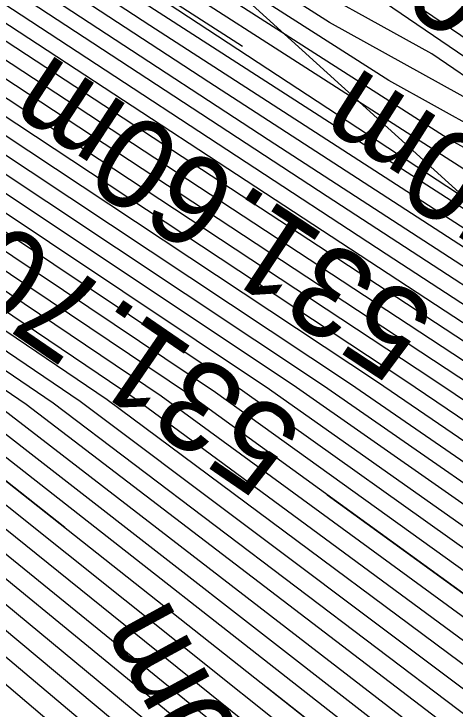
# Model space of a CAD drawing. Extents: x -866683 to -866410, y -1041951 to -1040252.
# Drawn here: x -866433.64 to -866432.173, y -1041927.226 to -1041924.913 of the extents above; entities that cross this region are included whole.
import ezdxf

# ---------------------------------------------------------------- set-up
doc = ezdxf.new("R2010")
doc.units = 0
for name, color, linetype in [('BREAKLINE', 7, 'Continuous'), ('V-VEDL', 7, 'Continuous'), ('V_po_cm', 7, 'Continuous')]:
    doc.layers.add(name, color=color, linetype=linetype)

msp = doc.modelspace()

# ---------------------------------------------------------------- linework, layer by layer
at = {"layer": 'BREAKLINE'}
msp.add_lwpolyline([(-866430.202, -1041927.282), (-866445.247, -1041913.64), (-866449.543, -1041926.354), (-866449.641, -1041934.033), (-866450.183, -1041936.864), (-866452.267, -1041937.851), (-866451.576, -1041945.087)], dxfattribs=at)
at = {"layer": 'V-VEDL'}
for points in [[(-866449.345, -1041907.5366), (-866448.9556, -1041907.8532), (-866448.4862, -1041908.0339), (-866448.3105, -1041908.3809), (-866448.4285, -1041908.8942), (-866448.8402, -1041909.5738), (-866449.0019, -1041910.1655), (-866448.9134, -1041910.6692), (-866448.5749, -1041911.085), (-866448.5335, -1041911.4362), (-866448.7893, -1041911.7228), (-866449.3421, -1041911.9448), (-866449.4057, -1041912.585), (-866448.98, -1041913.6435), (-866448.0652, -1041915.1203), (-866447.345, -1041916.0757), (-866446.8195, -1041916.5099), (-866446.4887, -1041916.4228), (-866444.7099, -1041917.3864), (-866441.483, -1041919.4008), (-866432.1333, -1041925.5308)], [(-866431.9788, -1041928.8199), (-866431.5928, -1041928.1776), (-866431.4675, -1041927.947), (-866431.4098, -1041927.8071), (-866431.4198, -1041927.7578), (-866431.4204, -1041927.6712), (-866431.4114, -1041927.5475), (-866431.3929, -1041927.3866), (-866433.06, -1041926.1783), (-866436.4127, -1041923.9225), (-866441.4509, -1041920.6192), (-866444.9601, -1041918.4567), (-866446.9402, -1041917.4347), (-866447.3913, -1041917.5535), (-866448.1079, -1041916.9614), (-866449.0899, -1041915.6585), (-866450.3375, -1041913.6448)], [(-866449.6588, -1041913.6442), (-866448.5775, -1041915.3894), (-866447.7264, -1041916.5186), (-866447.1054, -1041917.0317), (-866446.7144, -1041916.9288), (-866444.6833, -1041918.021), (-866441.0121, -1041920.3082), (-866435.7006, -1041923.7906), (-866432.1607, -1041926.1208), (-866430.3921, -1041927.2987), (-866430.3951, -1041927.3244), (-866430.3965, -1041927.3441), (-866430.3964, -1041927.358), (-866430.3948, -1041927.3658), (-866430.4041, -1041927.3882), (-866430.4241, -1041927.425), (-866430.4857, -1041927.5276)], [(-866449.6023, -1041915.9277), (-866448.4893, -1041917.4043), (-866447.6772, -1041918.0753), (-866447.1659, -1041917.9407), (-866445.2368, -1041918.8924), (-866441.8897, -1041920.9302), (-866437.1247, -1041924.0544), (-866433.9594, -1041926.2358), (-866432.3937, -1041927.4746), (-866432.4277, -1041927.7707), (-866432.4442, -1041927.9983), (-866432.4432, -1041928.1576), (-866432.4248, -1041928.2484), (-866432.531, -1041928.5059), (-866432.7616, -1041928.9302), (-866433.4719, -1041930.1123)]]:
    msp.add_lwpolyline(points, dxfattribs=at)
at = {"layer": 'V_po_cm'}
for points in [[(-866449.4813, -1041912.5658), (-866449.0479, -1041913.6436), (-866448.1164, -1041915.1472), (-866447.3831, -1041916.12), (-866446.8481, -1041916.5621), (-866446.5112, -1041916.4734), (-866444.7001, -1041917.4545), (-866441.4146, -1041919.5055), (-866436.6547, -1041922.6262), (-866433.3844, -1041924.7606), (-866431.6036, -1041925.9086), (-866431.3124, -1041926.0701), (-866431.0001, -1041926.2826), (-866430.6667, -1041926.546), (-866429.9578, -1041927.1745)], [(-866449.3301, -1041912.6042), (-866448.9122, -1041913.6435), (-866448.0139, -1041915.0933), (-866447.3068, -1041916.0314), (-866446.7909, -1041916.4577), (-866446.4661, -1041916.3722), (-866444.7196, -1041917.3183), (-866441.5514, -1041919.296), (-866436.9616, -1041922.3053), (-866433.7773, -1041924.3805), (-866431.9985, -1041925.5217), (-866431.6252, -1041925.7288), (-866431.2249, -1041926.0011), (-866430.7976, -1041926.3386), (-866429.889, -1041927.1442)], [(-866429.8546, -1041927.129), (-866430.8631, -1041926.2349), (-866431.3373, -1041925.8603), (-866431.7816, -1041925.5581), (-866432.1959, -1041925.3282), (-866433.9737, -1041924.1905), (-866437.115, -1041922.1448), (-866441.6199, -1041919.1913), (-866444.7294, -1041917.2502), (-866446.4435, -1041916.3216), (-866446.7623, -1041916.4055), (-866447.2687, -1041915.9871), (-866447.9627, -1041915.0664), (-866448.8443, -1041913.6434), (-866449.2545, -1041912.6234)], [(-866429.8202, -1041927.1139), (-866430.9285, -1041926.1313), (-866431.4498, -1041925.7195), (-866431.938, -1041925.3874), (-866432.3933, -1041925.1348), (-866434.1701, -1041924.0005), (-866437.2685, -1041921.9844), (-866441.6883, -1041919.0865), (-866444.7391, -1041917.1821), (-866446.4209, -1041916.271), (-866446.7337, -1041916.3534), (-866447.2305, -1041915.9429), (-866447.9114, -1041915.0395), (-866448.7764, -1041913.6433), (-866449.1788, -1041912.6426)], [(-866431.8295, -1041928.6907), (-866431.476, -1041928.1023), (-866431.3612, -1041927.8912), (-866431.3083, -1041927.763), (-866431.3175, -1041927.7178), (-866431.318, -1041927.6385), (-866431.3098, -1041927.5252), (-866431.2929, -1041927.3778), (-866432.9701, -1041926.1725), (-866436.3415, -1041923.9093), (-866441.407, -1041920.5881), (-866444.9324, -1041918.4131), (-866446.9176, -1041917.3841), (-866447.3627, -1041917.5013), (-866448.0697, -1041916.9172), (-866449.0387, -1041915.6316), (-866450.2696, -1041913.6447)], [(-866431.6802, -1041928.5615), (-866431.3591, -1041928.0271), (-866431.2548, -1041927.8353), (-866431.2068, -1041927.7188), (-866431.2152, -1041927.6778), (-866431.2156, -1041927.6058), (-866431.2081, -1041927.5029), (-866431.1928, -1041927.369), (-866432.8802, -1041926.1668), (-866436.2703, -1041923.8961), (-866441.3631, -1041920.557), (-866444.9047, -1041918.3695), (-866446.895, -1041917.3336), (-866447.3341, -1041917.4491), (-866448.0316, -1041916.8729), (-866448.9875, -1041915.6047), (-866450.2018, -1041913.6447)], [(-866450.1339, -1041913.6446), (-866448.9362, -1041915.5778), (-866447.9934, -1041916.8286), (-866447.3055, -1041917.397), (-866446.8725, -1041917.283), (-866444.877, -1041918.3259), (-866441.3192, -1041920.5259), (-866436.1991, -1041923.8829), (-866432.7902, -1041926.161), (-866431.0927, -1041927.3603), (-866431.1065, -1041927.4806), (-866431.1132, -1041927.5731), (-866431.1128, -1041927.6378), (-866431.1053, -1041927.6747), (-866431.1485, -1041927.7794), (-866431.2422, -1041927.9518), (-866431.5309, -1041928.4322)], [(-866431.3816, -1041928.303), (-866431.1253, -1041927.8766), (-866431.0421, -1041927.7235), (-866431.0038, -1041927.6306), (-866431.0105, -1041927.5978), (-866431.0108, -1041927.5404), (-866431.0049, -1041927.4583), (-866430.9926, -1041927.3515), (-866432.7003, -1041926.1553), (-866436.1279, -1041923.8697), (-866441.2754, -1041920.4948), (-866444.8494, -1041918.2824), (-866446.8499, -1041917.2324), (-866447.2769, -1041917.3448), (-866447.9553, -1041916.7843), (-866448.885, -1041915.5509), (-866450.066, -1041913.6445)], [(-866449.9981, -1041913.6445), (-866448.8337, -1041915.524), (-866447.9171, -1041916.74), (-866447.2483, -1041917.2926), (-866446.8273, -1041917.1818), (-866444.8217, -1041918.2388), (-866441.2315, -1041920.4637), (-866436.0567, -1041923.8566), (-866432.6103, -1041926.1495), (-866430.8925, -1041927.3427), (-866430.9032, -1041927.436), (-866430.9084, -1041927.5077), (-866430.9081, -1041927.5579), (-866430.9023, -1041927.5865), (-866430.9358, -1041927.6676), (-866431.0085, -1041927.8013), (-866431.2323, -1041928.1737)], [(-866449.9303, -1041913.6444), (-866448.7825, -1041915.4971), (-866447.879, -1041916.6957), (-866447.2197, -1041917.2404), (-866446.8047, -1041917.1312), (-866444.794, -1041918.1952), (-866441.1876, -1041920.4326), (-866435.9855, -1041923.8434), (-866432.5204, -1041926.1438), (-866430.7925, -1041927.3339), (-866430.8016, -1041927.4136), (-866430.8061, -1041927.475), (-866430.8058, -1041927.5179), (-866430.8008, -1041927.5423), (-866430.8294, -1041927.6117), (-866430.8916, -1041927.726), (-866431.0829, -1041928.0445)], [(-866430.9336, -1041927.9153), (-866430.7747, -1041927.6508), (-866430.7231, -1041927.5558), (-866430.6993, -1041927.4982), (-866430.7035, -1041927.4779), (-866430.7037, -1041927.4423), (-866430.7, -1041927.3913), (-866430.6924, -1041927.3251), (-866432.4305, -1041926.138), (-866435.9142, -1041923.8302), (-866441.1437, -1041920.4015), (-866444.7663, -1041918.1517), (-866446.7822, -1041917.0806), (-866447.1911, -1041917.1882), (-866447.8408, -1041916.6514), (-866448.7313, -1041915.4701), (-866449.8624, -1041913.6444)], [(-866430.7843, -1041927.786), (-866430.6578, -1041927.5755), (-866430.6167, -1041927.5), (-866430.5978, -1041927.4541), (-866430.6011, -1041927.4379), (-866430.6013, -1041927.4096), (-866430.5984, -1041927.369), (-866430.5923, -1041927.3163), (-866432.3405, -1041926.1323), (-866435.843, -1041923.817), (-866441.0998, -1041920.3704), (-866444.7387, -1041918.1081), (-866446.7596, -1041917.03), (-866447.1625, -1041917.1361), (-866447.8027, -1041916.6072), (-866448.68, -1041915.4432), (-866449.7945, -1041913.6443)], [(-866430.635, -1041927.6568), (-866430.5409, -1041927.5003), (-866430.5104, -1041927.4441), (-866430.4963, -1041927.41), (-866430.4988, -1041927.3979), (-866430.4989, -1041927.3769), (-866430.4967, -1041927.3467), (-866430.4922, -1041927.3075), (-866432.2506, -1041926.1265), (-866435.7718, -1041923.8038), (-866441.0559, -1041920.3393), (-866444.711, -1041918.0645), (-866446.737, -1041916.9794), (-866447.134, -1041917.0839), (-866447.7646, -1041916.5629), (-866448.6288, -1041915.4163), (-866449.7266, -1041913.6442)], [(-866449.5909, -1041913.6441), (-866448.5263, -1041915.3625), (-866447.6883, -1041916.4743), (-866447.0768, -1041916.9795), (-866446.6919, -1041916.8782), (-866444.6556, -1041917.9774), (-866440.9682, -1041920.2771), (-866435.6294, -1041923.7774), (-866432.0707, -1041926.115), (-866430.2921, -1041927.2899), (-866430.2935, -1041927.3021), (-866430.2941, -1041927.3114), (-866430.2941, -1041927.318), (-866430.2933, -1041927.3217), (-866430.2977, -1041927.3323), (-866430.3072, -1041927.3497), (-866430.3364, -1041927.3983)], [(-866430.1986, -1041927.2805), (-866430.2085, -1041927.2716), (-866430.2132, -1041927.2679), (-866430.2176, -1041927.2649), (-866430.2217, -1041927.2627), (-866432.0094, -1041926.0909), (-866435.5807, -1041923.7495), (-866440.9355, -1041920.2387), (-866444.6317, -1041917.9314), (-866446.6693, -1041916.8276), (-866447.0482, -1041916.9273), (-866447.6501, -1041916.43), (-866448.4751, -1041915.3356), (-866449.523, -1041913.644)], [(-866449.4552, -1041913.644), (-866448.4238, -1041915.3087), (-866447.612, -1041916.3857), (-866447.0196, -1041916.8752), (-866446.6467, -1041916.777), (-866444.6415, -1041917.8632), (-866441.004, -1041920.1339), (-866435.7341, -1041923.5891), (-866432.2058, -1041925.9008), (-866430.4192, -1041927.0692), (-866430.374, -1041927.0942), (-866430.3257, -1041927.1272), (-866430.274, -1041927.168), (-866430.1642, -1041927.2653)], [(-866449.3873, -1041913.6439), (-866448.3726, -1041915.2817), (-866447.5738, -1041916.3414), (-866446.991, -1041916.823), (-866446.6241, -1041916.7264), (-866444.6513, -1041917.7951), (-866441.0724, -1041920.0292), (-866435.8875, -1041923.4286), (-866432.4023, -1041925.7108), (-866430.6166, -1041926.8758), (-866430.5304, -1041926.9236), (-866430.4381, -1041926.9864), (-866430.3395, -1041927.0643), (-866430.1298, -1041927.2502)], [(-866430.0954, -1041927.2351), (-866430.4049, -1041926.9606), (-866430.5505, -1041926.8456), (-866430.6868, -1041926.7529), (-866430.814, -1041926.6823), (-866432.5987, -1041925.5207), (-866436.041, -1041923.2681), (-866441.1408, -1041919.9245), (-866444.661, -1041917.727), (-866446.6015, -1041916.6758), (-866446.9624, -1041916.7708), (-866447.5357, -1041916.2972), (-866448.3213, -1041915.2548), (-866449.3194, -1041913.6438)], [(-866449.2515, -1041913.6438), (-866448.2701, -1041915.2279), (-866447.4975, -1041916.2529), (-866446.9338, -1041916.7186), (-866446.579, -1041916.6252), (-866444.6708, -1041917.6589), (-866441.2093, -1041919.8197), (-866436.1944, -1041923.1077), (-866432.7951, -1041925.3307), (-866431.0114, -1041926.4889), (-866430.8432, -1041926.5822), (-866430.6629, -1041926.7049), (-866430.4704, -1041926.857), (-866430.061, -1041927.2199)], [(-866430.0266, -1041927.2048), (-866430.5358, -1041926.7533), (-866430.7753, -1041926.5641), (-866430.9996, -1041926.4115), (-866431.2088, -1041926.2954), (-866432.9916, -1041925.1407), (-866436.3479, -1041922.9472), (-866441.2777, -1041919.715), (-866444.6806, -1041917.5908), (-866446.5564, -1041916.5746), (-866446.9052, -1041916.6664), (-866447.4594, -1041916.2086), (-866448.2189, -1041915.201), (-866449.1837, -1041913.6437)], [(-866449.1158, -1041913.6437), (-866448.1676, -1041915.1741), (-866447.4212, -1041916.1643), (-866446.8766, -1041916.6143), (-866446.5338, -1041916.524), (-866444.6903, -1041917.5227), (-866441.3461, -1041919.6102), (-866436.5013, -1041922.7867), (-866433.188, -1041924.9506), (-866431.4062, -1041926.102), (-866431.156, -1041926.2408), (-866430.8877, -1041926.4234), (-866430.6013, -1041926.6496), (-866429.9922, -1041927.1896)], [(-866449.1412, -1041915.6855), (-866448.146, -1041917.0057), (-866447.4199, -1041917.6057), (-866446.9628, -1041917.4853), (-866444.9877, -1041918.5002), (-866441.4948, -1041920.6503), (-866436.4839, -1041923.9357), (-866433.15, -1041926.184), (-866431.493, -1041927.3954), (-866431.513, -1041927.5698), (-866431.5227, -1041927.7039), (-866431.5222, -1041927.7977), (-866431.5113, -1041927.8512), (-866431.5739, -1041928.0029), (-866431.7097, -1041928.2529), (-866432.1281, -1041928.9492)], [(-866449.1924, -1041915.7124), (-866448.1841, -1041917.05), (-866447.4485, -1041917.6579), (-866446.9853, -1041917.5359), (-866445.0154, -1041918.5438), (-866441.5387, -1041920.6814), (-866436.5551, -1041923.9489), (-866433.2399, -1041926.1898), (-866431.5931, -1041927.4042), (-866431.6146, -1041927.5922), (-866431.6251, -1041927.7367), (-866431.6245, -1041927.8377), (-866431.6128, -1041927.8953), (-866431.6802, -1041928.0588), (-866431.8266, -1041928.3281), (-866432.2774, -1041929.0784)], [(-866449.2436, -1041915.7393), (-866448.2223, -1041917.0943), (-866447.477, -1041917.71), (-866447.0079, -1041917.5865), (-866445.0431, -1041918.5874), (-866441.5825, -1041920.7125), (-866436.6263, -1041923.962), (-866433.3298, -1041926.1955), (-866431.6932, -1041927.413), (-866431.7163, -1041927.6145), (-866431.7275, -1041927.7694), (-866431.7269, -1041927.8777), (-866431.7143, -1041927.9395), (-866431.7866, -1041928.1147), (-866431.9435, -1041928.4034), (-866432.4267, -1041929.2077)], [(-866449.2949, -1041915.7662), (-866448.2604, -1041917.1386), (-866447.5056, -1041917.7622), (-866447.0305, -1041917.6371), (-866445.0708, -1041918.6309), (-866441.6264, -1041920.7436), (-866436.6975, -1041923.9752), (-866433.4198, -1041926.2013), (-866431.7932, -1041927.4218), (-866431.8179, -1041927.6368), (-866431.8299, -1041927.8021), (-866431.8292, -1041927.9177), (-866431.8158, -1041927.9836), (-866431.8929, -1041928.1706), (-866432.0603, -1041928.4786), (-866432.5761, -1041929.3369)], [(-866449.3461, -1041915.7931), (-866448.2986, -1041917.1829), (-866447.5342, -1041917.8144), (-866447.0531, -1041917.6877), (-866445.0984, -1041918.6745), (-866441.6703, -1041920.7747), (-866436.7687, -1041923.9884), (-866433.5097, -1041926.207), (-866431.8933, -1041927.4306), (-866431.9195, -1041927.6591), (-866431.9323, -1041927.8348), (-866431.9315, -1041927.9577), (-866431.9173, -1041928.0277), (-866431.9992, -1041928.2265), (-866432.1772, -1041928.5539), (-866432.7254, -1041929.4661)], [(-866432.8747, -1041929.5954), (-866432.2941, -1041928.6292), (-866432.1056, -1041928.2824), (-866432.0188, -1041928.0719), (-866432.0339, -1041927.9976), (-866432.0346, -1041927.8675), (-866432.0212, -1041927.6814), (-866431.9934, -1041927.4394), (-866433.5997, -1041926.2128), (-866436.8399, -1041924.0016), (-866441.7142, -1041920.8058), (-866445.1261, -1041918.7181), (-866447.0756, -1041917.7383), (-866447.5628, -1041917.8666), (-866448.3367, -1041917.2272), (-866449.3974, -1041915.82)], [(-866449.4486, -1041915.8469), (-866448.3749, -1041917.2714), (-866447.5914, -1041917.9188), (-866447.0982, -1041917.7889), (-866445.1538, -1041918.7616), (-866441.7581, -1041920.8369), (-866436.9111, -1041924.0148), (-866433.6896, -1041926.2185), (-866432.0935, -1041927.4482), (-866432.1228, -1041927.7037), (-866432.137, -1041927.9002), (-866432.1362, -1041928.0376), (-866432.1203, -1041928.116), (-866432.2119, -1041928.3383), (-866432.411, -1041928.7044), (-866433.024, -1041929.7246)], [(-866449.4998, -1041915.8738), (-866448.413, -1041917.3157), (-866447.62, -1041917.9709), (-866447.1208, -1041917.8395), (-866445.1814, -1041918.8052), (-866441.802, -1041920.868), (-866436.9823, -1041924.028), (-866433.7795, -1041926.2243), (-866432.1936, -1041927.457), (-866432.2244, -1041927.726), (-866432.2394, -1041927.9329), (-866432.2386, -1041928.0776), (-866432.2218, -1041928.1601), (-866432.3183, -1041928.3941), (-866432.5279, -1041928.7797), (-866433.1733, -1041929.8538)], [(-866433.3226, -1041929.9831), (-866432.6447, -1041928.855), (-866432.4246, -1041928.45), (-866432.3233, -1041928.2042), (-866432.3409, -1041928.1176), (-866432.3418, -1041927.9656), (-866432.326, -1041927.7483), (-866432.2936, -1041927.4658), (-866433.8695, -1041926.23), (-866437.0535, -1041924.0412), (-866441.8458, -1041920.8991), (-866445.2091, -1041918.8488), (-866447.1434, -1041917.8901), (-866447.6486, -1041918.0231), (-866448.4512, -1041917.36), (-866449.5511, -1041915.9008)], [(-866449.6536, -1041915.9546), (-866448.5274, -1041917.4486), (-866447.7058, -1041918.1275), (-866447.1885, -1041917.9913), (-866445.2645, -1041918.9359), (-866441.9336, -1041920.9613), (-866437.1959, -1041924.0675), (-866434.0493, -1041926.2415), (-866432.4938, -1041927.4834), (-866432.5293, -1041927.793), (-866432.5466, -1041928.031), (-866432.5456, -1041928.1975), (-866432.5263, -1041928.2925), (-866432.6373, -1041928.5618), (-866432.8785, -1041929.0055), (-866433.6212, -1041930.2416)], [(-866449.7048, -1041915.9815), (-866448.5656, -1041917.4929), (-866447.7344, -1041918.1797), (-866447.2111, -1041918.0419), (-866445.2921, -1041918.9795), (-866441.9775, -1041920.9924), (-866437.2672, -1041924.0807), (-866434.1393, -1041926.2473), (-866432.5939, -1041927.4921), (-866432.6309, -1041927.8153), (-866432.6489, -1041928.0637), (-866432.6479, -1041928.2375), (-866432.6278, -1041928.3366), (-866432.7437, -1041928.6177), (-866432.9954, -1041929.0807), (-866433.7706, -1041930.3708)], [(-866449.756, -1041916.0084), (-866448.6037, -1041917.5372), (-866447.7629, -1041918.2318), (-866447.2337, -1041918.0925), (-866445.3198, -1041919.0231), (-866442.0214, -1041921.0235), (-866437.3384, -1041924.0939), (-866434.2292, -1041926.253), (-866432.6939, -1041927.5009), (-866432.7326, -1041927.8376), (-866432.7513, -1041928.0964), (-866432.7503, -1041928.2775), (-866432.7293, -1041928.3807), (-866432.85, -1041928.6736), (-866433.1122, -1041929.156), (-866433.9199, -1041930.5)], [(-866434.0692, -1041930.6293), (-866433.2291, -1041929.2313), (-866432.9564, -1041928.7295), (-866432.8308, -1041928.4249), (-866432.8526, -1041928.3175), (-866432.8537, -1041928.1292), (-866432.8342, -1041927.8599), (-866432.794, -1041927.5097), (-866434.3192, -1041926.2588), (-866437.4096, -1041924.1071), (-866442.0653, -1041921.0546), (-866445.3475, -1041919.0666), (-866447.2562, -1041918.1431), (-866447.7915, -1041918.284), (-866448.6419, -1041917.5814), (-866449.8073, -1041916.0353)], [(-866434.2185, -1041930.7585), (-866433.346, -1041929.3065), (-866433.0627, -1041928.7853), (-866432.9323, -1041928.469), (-866432.9549, -1041928.3575), (-866432.9561, -1041928.1619), (-866432.9358, -1041927.8822), (-866432.8941, -1041927.5185), (-866434.4091, -1041926.2645), (-866437.4808, -1041924.1203), (-866442.1091, -1041921.0857), (-866445.3752, -1041919.1102), (-866447.2788, -1041918.1937), (-866447.8201, -1041918.3362), (-866448.68, -1041917.6257), (-866449.8585, -1041916.0622)], [(-866434.3678, -1041930.8878), (-866433.4629, -1041929.3818), (-866433.169, -1041928.8412), (-866433.0338, -1041928.5131), (-866433.0573, -1041928.3974), (-866433.0585, -1041928.1946), (-866433.0374, -1041927.9045), (-866432.9942, -1041927.5273), (-866434.499, -1041926.2703), (-866437.552, -1041924.1335), (-866442.153, -1041921.1168), (-866445.4028, -1041919.1538), (-866447.3014, -1041918.2443), (-866447.8487, -1041918.3884), (-866448.7182, -1041917.67), (-866449.9098, -1041916.0892)], [(-866434.5171, -1041931.017), (-866433.5798, -1041929.457), (-866433.2754, -1041928.8971), (-866433.1353, -1041928.5572), (-866433.1596, -1041928.4374), (-866433.1609, -1041928.2273), (-866433.1391, -1041927.9268), (-866433.0943, -1041927.5361), (-866434.589, -1041926.276), (-866437.6232, -1041924.1467), (-866442.1969, -1041921.1479), (-866445.4305, -1041919.1973), (-866447.324, -1041918.2949), (-866447.8773, -1041918.4406), (-866448.7563, -1041917.7143), (-866449.961, -1041916.1161)], [(-866450.0122, -1041916.143), (-866448.7945, -1041917.7586), (-866447.9059, -1041918.4927), (-866447.3465, -1041918.3455), (-866445.4582, -1041919.2409), (-866442.2408, -1041921.179), (-866437.6944, -1041924.1598), (-866434.6789, -1041926.2818), (-866433.1943, -1041927.5449), (-866433.2407, -1041927.9492), (-866433.2632, -1041928.26), (-866433.262, -1041928.4774), (-866433.2368, -1041928.6014), (-866433.3817, -1041928.953), (-866433.6966, -1041929.5323), (-866434.6664, -1041931.1462)], [(-866441.9621, -1041918.6676), (-866437.8822, -1041921.3425), (-866434.9558, -1041923.2403), (-866433.183, -1041924.361), (-866432.5636, -1041924.7046), (-866431.8994, -1041925.1565), (-866431.1904, -1041925.7166), (-866429.6826, -1041927.0533)], [(-866429.717, -1041927.0685), (-866431.1249, -1041925.8203), (-866431.787, -1041925.2973), (-866432.4072, -1041924.8753), (-866432.9855, -1041924.5545), (-866434.7594, -1041923.4304), (-866437.7288, -1041921.503), (-866441.8936, -1041918.7723)], [(-866429.7514, -1041927.0836), (-866431.0594, -1041925.9239), (-866431.6746, -1041925.438), (-866432.2508, -1041925.046), (-866432.7881, -1041924.7479), (-866434.563, -1041923.6204), (-866437.5753, -1041921.6634), (-866441.8252, -1041918.877)], [(-866429.7858, -1041927.0988), (-866430.994, -1041926.0276), (-866431.5622, -1041925.5788), (-866432.0944, -1041925.2167), (-866432.5907, -1041924.9414), (-866434.3665, -1041923.8104), (-866437.4219, -1041921.8239), (-866441.7568, -1041918.9818)], [(-866432.88, -1041925.0213), (-866433.5808, -1041924.5706), (-866436.4008, -1041922.7314)], [(-866433.4713, -1041926.622), (-866433.9594, -1041926.2358), (-866436.8287, -1041924.2584)], [(-866432.5989, -1041926.5125), (-866431.3929, -1041927.3866), (-866431.4114, -1041927.5475), (-866431.4204, -1041927.6712), (-866431.4198, -1041927.7578), (-866431.4098, -1041927.8071), (-866431.4675, -1041927.947), (-866431.5928, -1041928.1776), (-866431.9788, -1041928.8199)], [(-866432.4319, -1041927.8291), (-866432.4277, -1041927.7707), (-866432.3937, -1041927.4746), (-866432.7991, -1041927.1538)]]:
    msp.add_lwpolyline(points, dxfattribs=at)

# ---------------------------------------------------------------- texts
for s, rotation, p in [('531.40m', 142.5682, (-866431.2026, -1041925.3862)), ('531.60m', 146.6439, (-866432.2236, -1041925.8999)), ('531.50m', 147.6052, (-866431.1793, -1041925.9227)), ('531.70m', 145.5232, (-866432.6632, -1041926.2864)), ('531.80m', 118.5374, (-866432.3907, -1041928.2188))]:
    msp.add_text(s, height=0.3, rotation=rotation, dxfattribs=at).set_placement(p)

doc.saveas('drawing.dxf')
